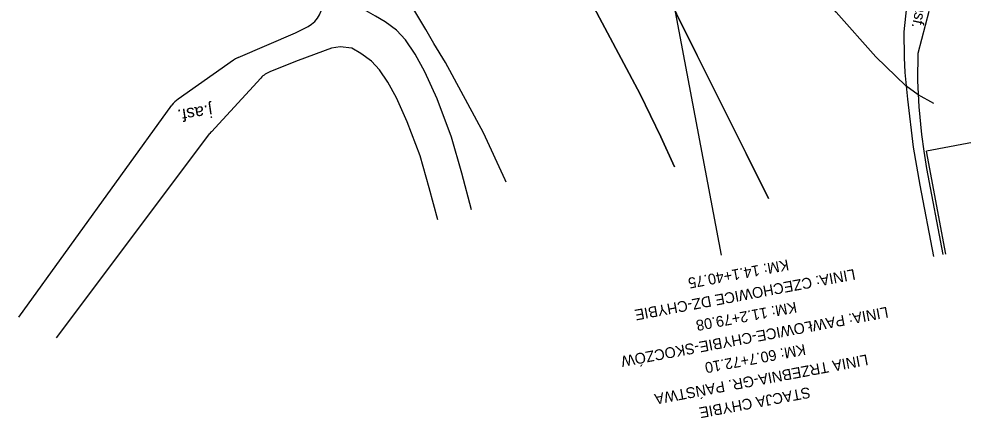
# Model space of a CAD drawing. Extents: x 6541740 to 6566395, y 5525066 to 5530361.
# Drawn here: x 6564292.2 to 6564401.8, y 5527739.5 to 5527785.7 of the extents above; entities that cross this region are included whole.
import ezdxf

# ---------------------------------------------------------------- set-up
doc = ezdxf.new("R2010")
doc.units = 0
for name, color, linetype in [('ps_wymiarowanie', 7, 'Continuous'), ('TOR_PRZEK_P-teren istniejacy', 7, 'Continuous'), ('TOR_PS_OPIS_T-numeracja torow i rozjazdow', 7, 'Continuous'), ('TOR_PS_T-rowy otwarte nieumocnione', 7, 'Continuous'), ('TOR_PS_T-wypelnienia', 7, 'Continuous')]:
    doc.layers.add(name, color=color, linetype=linetype)

msp = doc.modelspace()

# ---------------------------------------------------------------- linework, layer by layer
at = {"layer": 'ps_wymiarowanie'}
for p, q in [((6564395.65, 5527791.23), (6564394.91, 5527784.24)), ((6564396.58, 5527781.77), (6564397.86, 5527786.65)), ((6564324.31, 5527784.11), (6564325.79, 5527784.87)), ((6564394.91, 5527784.24), (6564394.94, 5527781.27)), ((6564317.67, 5527781.26), (6564324.31, 5527784.11)), ((6564328.51, 5527782.33), (6564324.65, 5527780.92)), ((6564317.13, 5527780.96), (6564310.7, 5527776.44)), ((6564394.94, 5527781.27), (6564395.01, 5527779.51)), ((6564396.52, 5527778.57), (6564396.58, 5527781.77)), ((6564324.65, 5527780.92), (6564321.41, 5527779.64)), ((6564320.3, 5527778.88), (6564314.58, 5527772.66)), ((6564395.01, 5527779.51), (6564395.34, 5527776.44)), ((6564396.69, 5527775.55), (6564396.52, 5527778.57)), ((6564292.24, 5527751.17), (6564310, 5527775.74)), ((6564395.34, 5527776.44), (6564395.99, 5527770.87)), ((6564397.01, 5527772.32), (6564396.69, 5527775.55)), ((6564296.61, 5527748.78), (6564314.39, 5527772.44)), ((6564397.28, 5527770.42), (6564397.01, 5527772.32)), ((6564406.79, 5527772.14), (6564397.54, 5527770.42)), ((6564395.99, 5527770.87), (6564396.78, 5527766.48)), ((6564397.59, 5527768.38), (6564397.28, 5527770.42)), ((6564399.8, 5527758.48), (6564397.54, 5527770.42)), ((6564399.48, 5527758.42), (6564397.59, 5527768.38)), ((6564396.78, 5527766.48), (6564398.34, 5527758.2))]:
    msp.add_line(p, q, dxfattribs=at)
for points in [[(6564344.75, 5527763.6), (6564343.62, 5527767.86), (6564342.42, 5527772.03), (6564340.75, 5527776.48), (6564339.33, 5527779.61), (6564338.21, 5527781.65), (6564337.11, 5527783.31), (6564336.03, 5527784.44), (6564334.74, 5527785.38), (6564333.6, 5527786.04), (6564331.44, 5527787.27)], [(6564340.84, 5527762.43), (6564339.85, 5527766.14), (6564338.78, 5527769.85), (6564337.3, 5527773.79), (6564336.03, 5527776.59), (6564335.04, 5527778.4), (6564334.08, 5527779.85), (6564333.13, 5527780.84), (6564331.91, 5527781.74), (6564330.86, 5527782.34), (6564329.52, 5527782.48), (6564328.51, 5527782.33), (6564328.51, 5527782.33)]]:
    msp.add_lwpolyline(points, dxfattribs=at)
at = {"layer": 'TOR_PS_OPIS_T-numeracja torow i rozjazdow'}
msp.add_lwpolyline([(6564373.75, 5527758.34), (6564351.45, 5527876.33), (6564349.06, 5527889.03), (6564345.47, 5527907.98)], dxfattribs=at)
at = {"layer": 'TOR_PS_T-rowy otwarte nieumocnione'}
for points in [[(6564356.94, 5527804.78), (6564360.12, 5527800.91), (6564363.13, 5527796.42), (6564366.13, 5527791.19), (6564370.93, 5527781.48), (6564376.62, 5527770.12), (6564379.21, 5527764.93)], [(6564379.21, 5527764.93), (6564376.62, 5527770.12), (6564370.93, 5527781.48), (6564366.13, 5527791.19), (6564363.13, 5527796.42), (6564360.12, 5527800.91), (6564356.94, 5527804.78)], [(6564395.16, 5527777.99), (6564391.66, 5527781.34), (6564387.05, 5527786.52), (6564383.96, 5527790.43), (6564379.96, 5527794.9), (6564372.73, 5527804.27)], [(6564395.16, 5527777.99), (6564391.66, 5527781.34), (6564387.05, 5527786.52), (6564383.96, 5527790.43), (6564379.96, 5527794.9), (6564372.73, 5527804.27)], [(6564348.79, 5527766.8), (6564348.67, 5527767.07), (6564346.14, 5527772.51), (6564341.72, 5527780.67), (6564340.39, 5527782.9), (6564339.44, 5527784.52), (6564338.17, 5527786.65), (6564336.32, 5527789.38), (6564334.24, 5527792.3), (6564330.19, 5527797.83)], [(6564368.32, 5527768.6), (6564366.72, 5527772.08), (6564364.3, 5527777), (6564358.33, 5527788.3), (6564357.85, 5527788.97), (6564356, 5527791.51), (6564352.04, 5527796.79)], [(6564352.04, 5527796.79), (6564356, 5527791.51), (6564357.85, 5527788.97), (6564358.33, 5527788.3), (6564364.3, 5527777), (6564366.72, 5527772.08), (6564368.32, 5527768.6)], [(6564398.39, 5527775.94), (6564396.56, 5527776.92), (6564395.16, 5527777.99)], [(6564398.39, 5527775.94), (6564396.56, 5527776.92), (6564395.16, 5527777.99)]]:
    msp.add_lwpolyline(points, dxfattribs=at)
at = {"layer": 'TOR_PS_T-wypelnienia'}
for centre, start, end in [((6564324.42, 5527787.54), 296.9963, 10.8133), ((6564318.85, 5527778.5), 113.2466, 125.134), ((6564322.51, 5527776.85), 111.4895, 137.3779), ((6564312.43, 5527773.98), 125.134, 144.1376), ((6564316.79, 5527770.63), 137.3779, 143.0685)]:
    msp.add_arc(centre, 3, start, end, dxfattribs=at)

# ---------------------------------------------------------------- texts
at = {"layer": 'TOR_PRZEK_P-teren istniejacy'}
for s, height, rotation, p in [('asf.', 1.302, 257.3504, (6564396.42, 5527787.53)), ('j.asf.', 1.443, 188.5696, (6564314.57, 5527775.8))]:
    msp.add_text(s, height=height, rotation=rotation, dxfattribs=at).set_placement(p)
at = {"layer": 'TOR_PS_OPIS_T-numeracja torow i rozjazdow'}
for s, p in [('KM: 14.1+40.75', (6564381.44, 5527757.86)), ('LINIA: CZECHOWICE DZ-CHYBIE', (6564389.15, 5527756.76)), ('KM: 11.2+79.08', (6564382.36, 5527752.95)), ('LINIA: PAWŁOWICE-CHYBIE-SKOCZÓW', (6564392.97, 5527752.38)), ('KM: 60.7+72.10', (6564383.39, 5527748.05)), ('LINIA TRZEBNIA-GR. PAŃSTWA', (6564390.63, 5527746.86)), ('STACJA CHYBIE', (6564383.95, 5527743.07))]:
    msp.add_text(s, height=1.25, rotation=190.5522, dxfattribs=at).set_placement(p)

doc.saveas('drawing.dxf')
